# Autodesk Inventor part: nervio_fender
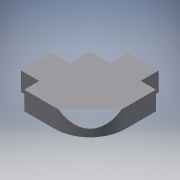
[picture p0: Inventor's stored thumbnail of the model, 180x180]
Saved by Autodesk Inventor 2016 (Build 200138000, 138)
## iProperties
Created: 2017-06
Part Number: nervio_fender
Material: Generic
Document SubType Name: Modeling
Designer: laboratorioesan
Density: 1 g/cm^3
Appearance: Default
Author: laboratorioesan
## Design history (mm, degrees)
sketch "Sketch1"
  geometry: L1 (0, 0)-(0, -30) reference; L2 (0, 0)-(-18.5, 0) reference; L3 (-18.5, -30)-(-18.5, 0) reference; L4 (0, -30)-(-18.5, -30) reference; L5 (50, 20)-(20, 20) reference; L6 (50, 20)-(50, 38.5) reference; L7 (20, 38.5)-(50, 38.5) reference; L8 (20, 20)-(20, 38.5) reference; L9 (0, 20.213)-(65, 20.213); L10 (65, 20.213)-(65, -44.787); L11 (65, -44.787)-(0, -44.787); L12 (0, -44.787)-(0, 20.213); L13 (20, 20)-(50, 20); L14 (50, 20)-(50, 38); L15 (50, 38)-(20, 38); L16 (20, 38)-(20, 20); L17 (0, 0)-(-18, 0); L18 (-18, 0)-(-18, -30); L19 (-18, -30)-(0, -30); L20 (0, -30)-(0, 0)
  constraints: 24 end point, 6 parallel, 3 horizontal, 3 perpendicular, 2 point on line
  dimensions: "d0" = 18 distance of L14.end L13.end; "d1" = 18 distance of L19.end L18.end; "d2" = 65 distance of L10.end L11.end; "d3" = 65 distance of L9.end L10.end
extrude "Extrusion1" new body sketch "Sketch1" distance "d4" = 18.5; taper "d5" = 0 deg
fillet "Fillet1" dims "d6" = 35
body "Solid1"
node "Reference1"
node "Reference2"
